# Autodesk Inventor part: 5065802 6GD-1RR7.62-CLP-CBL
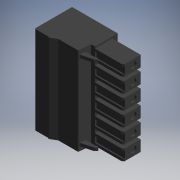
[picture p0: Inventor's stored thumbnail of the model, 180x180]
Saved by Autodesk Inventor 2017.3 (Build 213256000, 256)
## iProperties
Part Number: 5065802 6GD-1RR7.62-CLP-CBL
Material: Generic
Catalog Web Link: www.cadenas.de
Description: NEKM-C6 (p)-Terminal strip
Vendor: FESTO
Document SubType Name: Modeling
Designer: partserver
Manufacturer: FESTO
Mass: 21.6186 g
Surface Area: 92.1465 cm^2
Volume: 21.6186 cm^3
Density: 1 g/cm^3
Appearance: PSOLRGB-80-80-80
Category: PARTsolutions
Company: FESTO
Title: 5065802 6GD-1RR7.62-CLP-CBL
Author: Cadenas PARTsolutions
Comments: Terminal strip
PSOL_IDENT_0: {$CADENAS_DATA\23d-libs\festo\parts\n\nekm\parts\nekm_c6_parts.prj},199 {VTYP=3D},{NB=5065802 6GD-1R
PSOL_IDENT_1: R7.62-CLP-CBL},{LINA=5065802 6GD-1RR7.62-CLP-CBL},{NN=NEKM-C6 (p)},{DATE=16.05.2019 05:36:58},{GEOMD
PSOL_IDENT_2: ATE=16.05.2019 05:36:56},{VERSION=},{LINEID=90},{WBVAR=},{WBNUMERIC=}  {NB=5065802 6GD-1RR7.62-CLP-C
PSOL_IDENT_3: BL},{LINA=5065802 6GD-1RR7.62-CLP-CBL},{KT=DUMMY},{TNR=5065802},{TYP=6GD-1RR7.62-CLP-CBL},{VERS=5},{
PSOL_IDENT_4: N=6},{L=45.720},{L1=0.000}
NB: 5065802 6GD-1RR7.62-CLP-CBL
NN: NEKM-C6 (p)
NT: Terminal strip
NBSYN: $TNR. $TYP.
LINA: 5065802 6GD-1RR7.62-CLP-CBL
CATALOG: Festo
TNR: 5065802
TYP: 6GD-1RR7.62-CLP-CBL
VERS: 5
N: 6
L: 45.72
L1: 0
SUPPLIER: FESTO
ARTICLENO: 5065802 6GD-1RR7.62-CLP-CBL
BOMINFO: 5065802 6GD-1RR7.62-CLP-CBL
CREATOR: CADENAS GmbH
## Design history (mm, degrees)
sketch "Sketch_14"
  geometry: L1 (-14.7, -1.388)-(-13.7, -1.965); L2 (-13.7, -1.965)-(2, -1.965); L3 (2, -1.965)-(2.497, -7.644); L4 (2.995, -8.1)-(12.85, -8.1); L5 (12.85, -8.1)-(15.968, -9.9); L6 (15.968, -9.9)-(16.25, -9.9); L7 (16.45, -9.7)-(16.45, -9.6); L8 (16.45, -9.6)-(23.25, -9.6); L9 (23.75, -9.1)-(23.75, 9.9); L10 (23.75, 9.9)-(-14.7, 9.9); L11 (-14.7, 9.9)-(-14.7, -1.388); A1 r 0.5 centre (2.995, -7.6) between (2.497, -7.644) and (2.995, -8.1); A2 r 0.2 centre (16.25, -9.7) between (16.25, -9.9) and (16.45, -9.7); A3 r 0.5 centre (23.25, -9.1) between (23.25, -9.6) and (23.75, -9.1)
  constraints: 22 end point, 6 point on circle, 3 centre point
extrude "Extrusion1" join sketch "Sketch_14" stored distance "d0" = 45.72; taper "d1" = 0 deg
sketch "Sketch_4"
  geometry: L1 (-22.26, 6.014)-(-22.26, 3.186); L2 (-15.84, 3.186)-(-15.84, 6.014); A1 r 3.45 centre (-19.05, 4.45) between (-22.26, 3.186) and (-15.84, 3.186); A2 r 3.45 centre (-19.05, 4.75) between (-15.84, 6.014) and (-22.26, 6.014)
  constraints: 4 end point, 4 point on circle, 2 centre point
extrude "Extrusion2" cut sketch "Sketch_4" distance "d2" = 10; taper "d3" = 0 deg
pattern_linear "Rectangular Pattern1" dims "d6" = 7.62, "d9" = 0
sketch "Sketch_6"
  geometry: L1 (-20.9, -4.05)-(-17.2, -4.05); L2 (-17.2, -4.05)-(-17.2, -0.2); L3 (-17.2, -0.2)-(-20.9, -0.2); L4 (-20.9, -0.2)-(-20.9, -4.05)
  constraints: 8 end point
extrude "Extrusion3" cut sketch "Sketch_6" distance "d10" = 7; taper "d11" = 0 deg
pattern_linear "Rectangular Pattern2" dims "d14" = 7.62, "d17" = 0
sketch "Sketch_15"
  geometry: L1 (-22.86, -3.965)-(22.86, -3.965); L2 (22.86, -3.965)-(22.86, 9.9); L3 (22.86, 9.9)-(-22.86, 9.9); L4 (-22.86, 9.9)-(-22.86, -3.965); L5 (16.2, -1.965)-(17.53, -1.965); L6 (17.53, -1.965)-(17.53, -1.772); L7 (17.485, -1.648)-(17.245, -1.362); L8 (17.393, -1.044)-(20.707, -1.044); L9 (20.855, -1.362)-(20.615, -1.648); L10 (20.57, -1.772)-(20.57, -1.965); L11 (20.57, -1.965)-(21.9, -1.965); L12 (21.9, -1.965)-(21.9, 7.165); L13 (21.9, 7.165)-(16.2, 7.165); L14 (16.2, 7.165)-(16.2, -1.965); L15 (8.58, -1.965)-(9.91, -1.965); L16 (9.91, -1.965)-(9.91, -1.772); L17 (9.865, -1.648)-(9.625, -1.362); L18 (9.773, -1.044)-(13.087, -1.044); L19 (13.235, -1.362)-(12.995, -1.648); L20 (12.95, -1.772)-(12.95, -1.965); L21 (12.95, -1.965)-(14.28, -1.965); L22 (14.28, -1.965)-(14.28, 7.165); L23 (14.28, 7.165)-(8.58, 7.165); L24 (8.58, 7.165)-(8.58, -1.965); L25 (0.96, -1.965)-(2.29, -1.965); L26 (2.29, -1.965)-(2.29, -1.772); L27 (2.245, -1.648)-(2.005, -1.362); L28 (2.153, -1.044)-(5.467, -1.044); L29 (5.615, -1.362)-(5.375, -1.648); L30 (5.33, -1.772)-(5.33, -1.965); L31 (5.33, -1.965)-(6.66, -1.965); L32 (6.66, -1.965)-(6.66, 7.165); L33 (6.66, 7.165)-(0.96, 7.165); L34 (0.96, 7.165)-(0.96, -1.965); L35 (-6.66, -1.965)-(-5.33, -1.965); L36 (-5.33, -1.965)-(-5.33, -1.772); L37 (-5.375, -1.648)-(-5.615, -1.362); L38 (-5.467, -1.044)-(-2.153, -1.044); L39 (-2.005, -1.362)-(-2.245, -1.648); L40 (-2.29, -1.772)-(-2.29, -1.965); L41 (-2.29, -1.965)-(-0.96, -1.965); L42 (-0.96, -1.965)-(-0.96, 7.165); L43 (-0.96, 7.165)-(-6.66, 7.165); L44 (-6.66, 7.165)-(-6.66, -1.965); L45 (-14.28, -1.965)-(-12.95, -1.965); L46 (-12.95, -1.965)-(-12.95, -1.772); L47 (-12.995, -1.648)-(-13.235, -1.362); L48 (-13.087, -1.044)-(-9.773, -1.044); L49 (-9.625, -1.362)-(-9.865, -1.648); L50 (-9.91, -1.772)-(-9.91, -1.965); L51 (-9.91, -1.965)-(-8.58, -1.965); L52 (-8.58, -1.965)-(-8.58, 7.165); L53 (-8.58, 7.165)-(-14.28, 7.165); L54 (-14.28, 7.165)-(-14.28, -1.965); L55 (-21.9, 7.165)-(-21.9, -1.965); L56 (-21.9, -1.965)-(-20.57, -1.965); L57 (-20.57, -1.965)-(-20.57, -1.772); L58 (-20.615, -1.648)-(-20.855, -1.362); L59 (-20.707, -1.044)-(-17.393, -1.044); L60 (-17.245, -1.362)-(-17.485, -1.648); L61 (-17.53, -1.772)-(-17.53, -1.965); L62 (-17.53, -1.965)-(-16.2, -1.965); L63 (-16.2, -1.965)-(-16.2, 7.165); L64 (-16.2, 7.165)-(-21.9, 7.165); A1 r 0.194 centre (17.336, -1.772) between (17.53, -1.772) and (17.485, -1.648); A2 r 0.193 centre (17.393, -1.237) between (17.393, -1.044) and (17.245, -1.362); A3 r 0.193 centre (20.707, -1.237) between (20.855, -1.362) and (20.707, -1.044); A4 r 0.194 centre (20.764, -1.772) between (20.615, -1.648) and (20.57, -1.772); A5 r 0.193 centre (9.717, -1.772) between (9.91, -1.772) and (9.865, -1.648); A6 r 0.194 centre (9.773, -1.238) between (9.773, -1.044) and (9.625, -1.362); A7 r 0.193 centre (13.087, -1.237) between (13.235, -1.362) and (13.087, -1.044); A8 r 0.194 centre (13.144, -1.772) between (12.995, -1.648) and (12.95, -1.772); A9 r 0.193 centre (2.097, -1.772) between (2.29, -1.772) and (2.245, -1.648); A10 r 0.194 centre (2.153, -1.238) between (2.153, -1.044) and (2.005, -1.362); A11 r 0.193 centre (5.467, -1.237) between (5.615, -1.362) and (5.467, -1.044); A12 r 0.193 centre (5.523, -1.772) between (5.375, -1.648) and (5.33, -1.772); A13 r 0.193 centre (-5.523, -1.772) between (-5.33, -1.772) and (-5.375, -1.648); A14 r 0.194 centre (-5.467, -1.238) between (-5.467, -1.044) and (-5.615, -1.362); A15 r 0.193 centre (-2.153, -1.237) between (-2.005, -1.362) and (-2.153, -1.044); A16 r 0.193 centre (-2.097, -1.772) between (-2.245, -1.648) and (-2.29, -1.772); A17 r 0.194 centre (-13.144, -1.772) between (-12.95, -1.772) and (-12.995, -1.648); A18 r 0.193 centre (-13.087, -1.237) between (-13.087, -1.044) and (-13.235, -1.362); A19 r 0.194 centre (-9.773, -1.238) between (-9.625, -1.362) and (-9.773, -1.044); A20 r 0.193 centre (-9.717, -1.772) between (-9.865, -1.648) and (-9.91, -1.772); A21 r 0.194 centre (-20.764, -1.772) between (-20.57, -1.772) and (-20.615, -1.648); A22 r 0.193 centre (-20.707, -1.237) between (-20.707, -1.044) and (-20.855, -1.362); A23 r 0.193 centre (-17.393, -1.237) between (-17.245, -1.362) and (-17.393, -1.044); A24 r 0.194 centre (-17.336, -1.772) between (-17.485, -1.648) and (-17.53, -1.772)
  constraints: 128 end point, 48 point on circle, 24 centre point
extrude "Extrusion4" cut sketch "Sketch_15" distance "d18" = 14.7; taper "d19" = 0 deg
sketch "Sketch5"
  geometry: 1 further point
hole "Hole1" sketch "Sketch5" at (-2.85, 4.788) diameter "d20" = 3.2; stored, may be unused: countersink angle "d24" = 90 deg, drill point angle "d26" = 0 deg; dims "d21" = 6, "d22" = 4, "d23" = 2, "d25" = 1
pattern_linear "Rectangular Pattern3" dims "d29" = 7.62, "d32" = 0
sketch "Sketch_18"
  geometry: L1 (-4.401, -4.881)-(-3.61, -5.671); L2 (-3.274, -5.865)-(2.476, -7.406); L3 (2.476, -7.406)-(2.241, -4.715); L4 (2.241, -4.715)-(-3.03, -4.485); L5 (-3.03, -4.485)-(-3.302, -4.213); L6 (-3.664, -4.165)-(-4.359, -4.566); A1 r 0.2 centre (-4.259, -4.74) between (-4.359, -4.566) and (-4.401, -4.881); A2 r 0.75 centre (-3.08, -5.141) between (-3.61, -5.671) and (-3.274, -5.865); A3 r 0.3 centre (-3.514, -4.425) between (-3.302, -4.213) and (-3.664, -4.165)
  constraints: 12 end point, 6 point on circle, 3 centre point
extrude "Extrusion5" join sketch "Sketch_18" distance "d33" = 1.6; taper "d34" = 0 deg
sketch "Sketch_19"
  geometry: L1 (-4.401, -4.881)-(-3.61, -5.671); L2 (-3.274, -5.865)-(2.476, -7.406); L3 (2.476, -7.406)-(2.241, -4.715); L4 (2.241, -4.715)-(-3.03, -4.485); L5 (-3.03, -4.485)-(-3.302, -4.213); L6 (-3.664, -4.165)-(-4.359, -4.566); A1 r 0.2 centre (-4.259, -4.74) between (-4.359, -4.566) and (-4.401, -4.881); A2 r 0.75 centre (-3.08, -5.141) between (-3.61, -5.671) and (-3.274, -5.865); A3 r 0.3 centre (-3.514, -4.425) between (-3.302, -4.213) and (-3.664, -4.165)
  constraints: 12 end point, 6 point on circle, 3 centre point
extrude "Extrusion6" join sketch "Sketch_19" distance "d35" = 1.6; taper "d36" = 0 deg
node "ANBAU_XY"
node "ANBAU_YZ"
node "ANBAU_ZX"
node "ANBAU_X"
node "ANBAU_Y"
node "ANBAU_Z"
node "ANBAU_Center"
body "Solid1"
